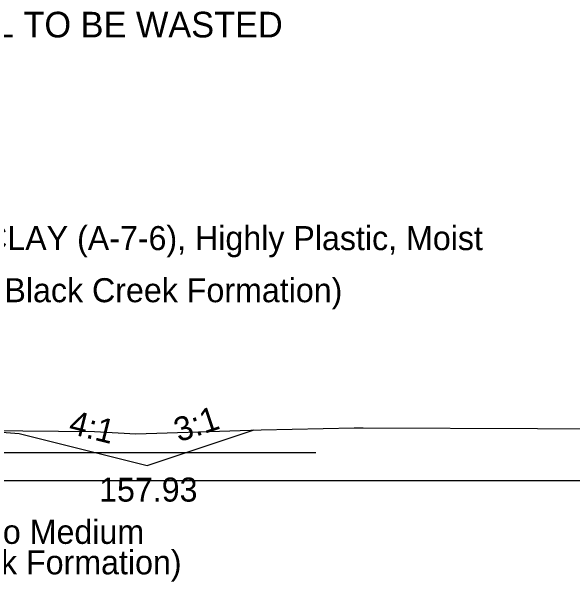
# Model space of a CAD drawing. Extents: x -516 to 303, y -10 to 5017.
# Drawn here: x 168.11 to 203.1, y 3993.69 to 4029.26 of the extents above; entities that cross this region are included whole.
import ezdxf

# ---------------------------------------------------------------- set-up
doc = ezdxf.new("R2010")
doc.units = 0
for name, color, linetype in [('Exist Cross Section Cell', 7, 'Continuous'), ('Exist XS Ground Line', 7, 'Continuous'), ('Prop CMT Slope Grass', 7, 'Continuous'), ('Prop Road Sect_ Material - Contact (General - Minor)', 7, 'Continuous'), ('Prop Road Sect_ Material - Tx (Composite Desc)', 7, 'Continuous'), ('Prop Road Sect_ Recs - UUC (Tx)', 7, 'Continuous'), ('Prop XS Ditch Standard Text', 7, 'Continuous'), ('Prop XS Side Slope Text', 7, 'Continuous'), ('Scratch_Level_0', 7, 'Continuous')]:
    doc.layers.add(name, color=color, linetype=linetype)

msp = doc.modelspace()

# ---------------------------------------------------------------- linework, layer by layer
at = {"layer": 'Exist Cross Section Cell'}
msp.add_line((150, 4000), (300, 4000), dxfattribs=at)
at = {"layer": 'Exist XS Ground Line'}
msp.add_lwpolyline([(162.102, 4003.161), (173.298, 4003.043), (175.868, 4002.91), (183.691, 4003.161), (189.487, 4003.273), (190.054, 4003.28), (211.786, 4003.196)], dxfattribs=at)
at = {"layer": 'Prop CMT Slope Grass'}
for p, q in [((162.587, 4003.406), (168.587, 4002.926)), ((176.587, 4000.926), (183.247, 4003.146)), ((168.587, 4002.926), (176.587, 4000.926))]:
    msp.add_line(p, q, dxfattribs=at)
at = {"layer": 'Prop Road Sect_ Material - Contact (General - Minor)'}
msp.add_line((115.068, 4001.737), (187.085, 4001.737), dxfattribs=at)

# ---------------------------------------------------------------- texts
at = {"layer": 'Prop Road Sect_ Material - Tx (Composite Desc)'}
for s, p in [('ROADWAY EMBANKMENT: Brown, Medium Stiff to Stiff, Silty CLAY (A-7-6), Highly Plastic, Moist', (110.569, 4014.367)), ('COASTAL PLAIN: Black to Gray, Stiff, Sandy SILT (A-4), Moist (Black Creek Formation)', (110.494, 4011.117)), ('COASTAL PLAIN: Orange-Brown and Gray, Soft to Medium ', (123.1, 3996.04)), ('Stiff, Sandy CLAY (A-6), Moist to Wet (Black Creek Formation)', (123.1, 3994.139))]:
    msp.add_text(s, height=1.5, dxfattribs=at).set_placement(p)
at = {"layer": 'Prop Road Sect_ Recs - UUC (Tx)'}
msp.add_text('END UNSUITABLE UNCLASSIFIED EXCAVATION-MATERIAL TO BE WASTED', height=1.6, dxfattribs=at).set_placement((107.755, 4027.638))
at = {"layer": 'Prop XS Ditch Standard Text'}
msp.add_text('157.93', height=1.5, dxfattribs=at).set_placement((173.581, 3998.676))
at = {"layer": 'Prop XS Side Slope Text'}
for s, rotation, p in [('3:1', 18.4332, (178.552, 4002.372)), ('4:1', 345.9638, (171.615, 4002.942))]:
    msp.add_text(s, height=1.5, rotation=rotation, dxfattribs=at).set_placement(p)
at = {"layer": 'Scratch_Level_0'}
for s, p in [('RT_Slope_Cut', (183.143, 4003.136)), ('RT_GS_OS_CTL', (168.48, 4002.916)), ('RT_SS_Ditch_Base_Out', (176.407, 4000.916))]:
    msp.add_text(s, height=0.02, dxfattribs=at).set_placement(p)

doc.saveas('drawing.dxf')
